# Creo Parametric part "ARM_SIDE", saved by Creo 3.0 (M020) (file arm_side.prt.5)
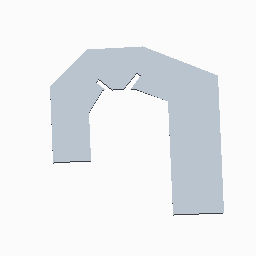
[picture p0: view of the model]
Units: millimeter Newton Second (mmNs); MM, TONNE, SECS

Created from: MMNS_PART_SOLID.PRT

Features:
  1. datum plane "RIGHT"
  2. datum plane "TOP"
  3. datum plane "FRONT"
  4. coordinate system
  5. sketch "Sketch 1"
  6. extrusion "Extrude 1"
  7. sketch "Sketch 2"
  8. sketch "Sketch 3"
  9. extruded cut "Extrude 3"
  10. sketch "Sketch 4"
  11. extruded cut "Extrude 4"

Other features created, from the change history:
  datum plane "DTM1"
  sketch "Sketch 2"
  extruded cut "Extrude 2"
  extruded cut "Extrude 3"

Surfaces: 24 plane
